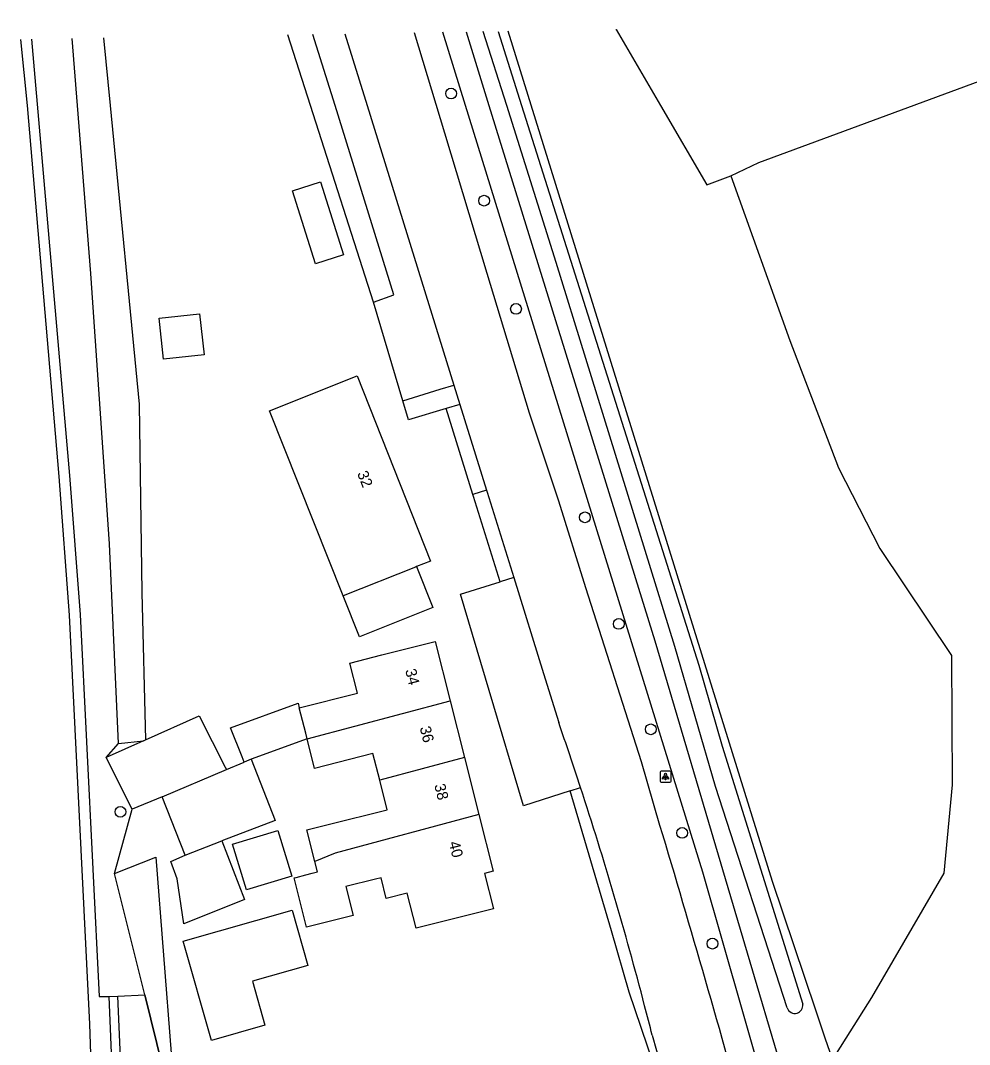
# Model space of a CAD drawing. Extents: x 162515 to 163909, y 388494 to 389773.
# Drawn here: x 162585.3 to 162671.5, y 389664.8 to 389757.7 of the extents above; entities that cross this region are included whole.
import ezdxf

# ---------------------------------------------------------------- set-up
doc = ezdxf.new("R2010")
doc.units = 0
for name, color, linetype in [('IMGEO_Boom', 7, 'Continuous'), ('IMGEO_Fietspad_gesloten', 7, 'Continuous'), ('IMGEO_Grasland_agrarisch', 7, 'Continuous'), ('IMGEO_Grasland_overig', 7, 'Continuous'), ('IMGEO_Groenvoorziening', 7, 'Continuous'), ('IMGEO_Haag', 7, 'Continuous'), ('IMGEO_Hek', 7, 'Continuous'), ('IMGEO_Lichtpunt', 7, 'Continuous'), ('IMGEO_Pand', 7, 'Continuous'), ('IMGEO_Pand_nummerreeks', 7, 'Continuous'), ('IMGEO_Rijbaan_lokaal_gesloten', 7, 'Continuous'), ('IMGEO_Rijbaan_lokaal_halfverhard', 7, 'Continuous'), ('IMGEO_Rijbaan_lokaal_open', 7, 'Continuous'), ('IMGEO_Rijbaan_regionaal_gesloten', 7, 'Continuous'), ('IMGEO_Voetpad_halfverhard', 7, 'Continuous'), ('IMGEO_Waterloop', 7, 'Continuous')]:
    doc.layers.add(name, color=color, linetype=linetype)

msp = doc.modelspace()

# ---------------------------------------------------------------- linework, layer by layer
at = {"layer": 'IMGEO_Boom'}
for centre in [(162624.392, 389751.1), (162627.393, 389741.373), (162630.292, 389731.545), (162636.548, 389712.625), (162639.625, 389702.949), (162642.53, 389693.381), (162594.354, 389685.892), (162645.384, 389683.977), (162648.134, 389673.926)]:
    msp.add_circle(centre, 0.489, dxfattribs=at)
at = {"layer": 'IMGEO_Fietspad_gesloten'}
for points in [[(162657.306, 389644.486), (162657.276, 389644.598), (162654.694, 389654.432), (162647.267, 389680.414), (162625.711, 389750), (162623.648, 389756.662)], [(162625.756, 389756.697), (162627.834, 389750), (162642.905, 389701.409), (162656.158, 389656.625)]]:
    msp.add_lwpolyline(points, dxfattribs=at)
at = {"layer": 'IMGEO_Grasland_agrarisch'}
for points in [[(162649.788, 389743.642), (162652.361, 389744.846), (162687.277, 389757.733)], [(162649.788, 389743.642), (162655.173, 389728.688), (162659.589, 389717.108), (162663.344, 389709.783), (162669.846, 389700.093), (162669.917, 389688.356), (162669.136, 389680.314), (162662.579, 389669.049), (162659.003, 389663.387)]]:
    msp.add_lwpolyline(points, dxfattribs=at)
at = {"layer": 'IMGEO_Grasland_overig'}
for points in [[(162593.826, 389680.304), (162597.563, 389681.786), (162598.974, 389663.973), (162599.575, 389661.2), (162600.194, 389654.868)], [(162596.561, 389669.268), (162593.826, 389680.304)], [(162596.561, 389669.268), (162599.268, 389658.347), (162600.194, 389654.868)]]:
    msp.add_lwpolyline(points, dxfattribs=at)
at = {"layer": 'IMGEO_Groenvoorziening'}
for points in [[(162659.003, 389663.387), (162658.792, 389664.143), (162658.415, 389665.263), (162657.534, 389667.881), (162653.602, 389679.561), (162629.565, 389756.763)], [(162639.372, 389756.927), (162639.379, 389756.914), (162643.424, 389750), (162647.635, 389742.802), (162649.788, 389743.642)], [(162586.279, 389756.033), (162589.745, 389716.421), (162590.687, 389703.802), (162592.43, 389669.135), (162593.333, 389669.135)], [(162620.012, 389723.199), (162617.339, 389732.159)], [(162626.377, 389714.707), (162623.952, 389722.498)], [(162593.056, 389690.825), (162594.171, 389692.08)], [(162593.826, 389680.304), (162595.429, 389686.12)], [(162594.132, 389669.168), (162596.561, 389669.268)]]:
    msp.add_lwpolyline(points, dxfattribs=at)
at = {"layer": 'IMGEO_Haag'}
for points in [[(162593.333, 389669.135), (162594.132, 389669.168)], [(162595.134, 389637.214), (162594.772, 389645.635), (162593.95, 389654.473), (162593.333, 389669.135)], [(162595.932, 389637.293), (162595.57, 389645.689), (162594.748, 389654.527), (162594.132, 389669.168)]]:
    msp.add_lwpolyline(points, dxfattribs=at)
at = {"layer": 'IMGEO_Hek'}
for points in [[(162593.826, 389680.304), (162597.563, 389681.786)], [(162596.561, 389669.268), (162593.826, 389680.304)], [(162600.194, 389654.868), (162599.268, 389658.347), (162596.561, 389669.268)]]:
    msp.add_lwpolyline(points, dxfattribs=at)
at = {"layer": 'IMGEO_Lichtpunt'}
for p, q in [((162643.373, 389689.494), (162643.373, 389688.687)), ((162643.373, 389689.494), (162643.373, 389688.687)), ((162644.275, 389689.589), (162643.467, 389689.589)), ((162644.275, 389689.589), (162643.467, 389689.589)), ((162644.369, 389688.687), (162644.369, 389689.494)), ((162644.369, 389688.687), (162644.369, 389689.494)), ((162643.467, 389688.593), (162644.275, 389688.593)), ((162643.467, 389688.593), (162644.275, 389688.593))]:
    msp.add_line(p, q, dxfattribs=at)
for points in [[(162643.747, 389689.158), (162643.786, 389689.13), (162643.598, 389688.868), (162643.56, 389688.895), (162643.747, 389689.158)], [(162643.849, 389689.11), (162643.896, 389689.11), (162643.896, 389688.788), (162643.849, 389688.788), (162643.849, 389689.11)], [(162643.959, 389689.13), (162643.997, 389689.157), (162644.184, 389688.895), (162644.145, 389688.867), (162643.959, 389689.13)]]:
    msp.add_lwpolyline(points, dxfattribs=at)
msp.add_circle((162643.872, 389689.292), 0.0994, dxfattribs=at)
for centre, start, end in [((162643.467, 389689.494), 90, 180), ((162643.467, 389689.494), 90, 180), ((162644.275, 389689.494), 0, 90), ((162644.275, 389689.494), 0, 90), ((162643.467, 389688.687), 180, 270), ((162643.467, 389688.687), 180, 270), ((162644.275, 389688.687), 270, 0), ((162644.275, 389688.687), 270, 360)]:
    msp.add_arc(centre, 0.0946, start, end, dxfattribs=at)
at = {"layer": 'IMGEO_Pand'}
for points in [[(162609.981, 389742.277), (162612.545, 389743.081), (162614.626, 389736.448), (162612.061, 389735.643), (162609.981, 389742.277)], [(162598.275, 389726.987), (162597.869, 389730.701), (162601.554, 389731.103), (162601.959, 389727.389), (162598.275, 389726.987)], [(162614.591, 389705.496), (162607.907, 389722.307), (162615.852, 389725.465), (162622.536, 389708.654), (162621.265, 389708.149)], [(162621.265, 389708.149), (162621.152, 389708.104), (162614.591, 389705.496)], [(162621.265, 389708.149), (162622.743, 389704.431), (162616.069, 389701.778), (162614.591, 389705.496)], [(162610.605, 389695.335), (162615.887, 389696.671), (162615.181, 389699.399), (162618.089, 389700.135), (162622.936, 389701.361), (162624.3, 389695.971)], [(162611.317, 389692.522), (162624.3, 389695.971)], [(162624.3, 389695.971), (162625.603, 389690.821)], [(162605.601, 389690.405), (162605.508, 389690.639), (162605.409, 389690.888), (162604.368, 389693.513), (162610.501, 389695.746), (162610.605, 389695.335)], [(162611.317, 389692.522), (162611.188, 389693.03), (162610.605, 389695.335)], [(162596.643, 389692.431), (162601.515, 389694.611), (162603.867, 389689.948), (162603.981, 389689.723)], [(162596.457, 389692.347), (162593.056, 389690.825)], [(162596.457, 389692.347), (162596.643, 389692.431)], [(162611.317, 389692.522), (162606.219, 389690.666)], [(162617.91, 389688.761), (162617.299, 389691.177), (162611.997, 389689.835), (162611.317, 389692.522)], [(162595.429, 389686.12), (162593.056, 389690.825)], [(162606.219, 389690.666), (162608.426, 389685.101), (162603.581, 389683.243)], [(162603.981, 389689.723), (162605.601, 389690.405)], [(162606.219, 389690.666), (162605.601, 389690.405)], [(162625.603, 389690.821), (162617.91, 389688.761)], [(162625.603, 389690.821), (162626.911, 389685.654)], [(162598.138, 389687.261), (162603.981, 389689.723)], [(162612.029, 389681.374), (162611.304, 389684.242), (162613.217, 389684.726), (162618.587, 389686.084), (162617.91, 389688.761)], [(162598.138, 389687.261), (162595.429, 389686.12)], [(162600.239, 389681.962), (162598.138, 389687.261)], [(162626.911, 389685.654), (162628.217, 389680.492), (162627.441, 389680.296), (162628.251, 389677.097), (162621.222, 389675.319), (162620.413, 389678.518), (162618.51, 389678.037), (162618.038, 389679.908), (162617.516, 389679.776), (162614.83, 389679.097), (162615.49, 389676.489), (162611.263, 389675.42), (162610.133, 389679.889), (162610.332, 389679.939), (162611.202, 389680.161), (162611.785, 389680.309), (162612.267, 389680.432), (162612.029, 389681.374)], [(162626.911, 389685.654), (162613.873, 389682.136), (162612.029, 389681.374)], [(162609.932, 389680.059), (162605.823, 389678.797), (162604.551, 389682.941), (162608.66, 389684.203), (162609.932, 389680.059)], [(162603.581, 389683.243), (162605.613, 389677.944), (162600.102, 389675.712), (162599.507, 389679.81), (162598.929, 389681.368), (162600.239, 389681.962)], [(162600.239, 389681.962), (162603.581, 389683.243)], [(162609.959, 389676.965), (162611.384, 389671.941), (162606.351, 389670.514), (162607.487, 389666.51), (162602.619, 389665.13), (162600.059, 389674.158), (162609.959, 389676.965)]]:
    msp.add_lwpolyline(points, dxfattribs=at)
at = {"layer": 'IMGEO_Rijbaan_lokaal_gesloten'}
for points in [[(162614.746, 389756.512), (162616.763, 389750), (162624.646, 389724.639)], [(162643.356, 389684.664), (162641.701, 389690.442), (162636.629, 389706.24), (162634.181, 389714.087), (162631.516, 389722.082), (162627.663, 389734.752), (162623.811, 389747.513), (162621.069, 389756.619)], [(162624.646, 389724.639), (162625.196, 389722.87)], [(162625.196, 389722.87), (162627.614, 389715.092)], [(162627.614, 389715.092), (162627.673, 389714.901), (162630.082, 389707.151)], [(162630.082, 389707.151), (162632.791, 389698.435), (162634.173, 389693.988)], [(162642.662, 389665.619), (162643.825, 389661.448)]]:
    msp.add_lwpolyline(points, dxfattribs=at)
for centre, radius, start, end in [((162310.638, 389581.786), 342.438, 18.08773, 19.12653), ((162307.447, 389580.769), 345.788, 14.66153, 18.08373), ((161544.624, 389352.917), 1147.723, 15.337949, 16.800985), ((162297.232, 389578.23), 356.312, 14.19723, 14.64087)]:
    msp.add_arc(centre, radius, start, end, dxfattribs=at)
at = {"layer": 'IMGEO_Rijbaan_lokaal_halfverhard'}
msp.add_lwpolyline([(162642.776, 389663.003), (162640.565, 389669.518), (162638.969, 389675.09), (162635.223, 389687.803)], dxfattribs=at)
at = {"layer": 'IMGEO_Rijbaan_lokaal_open'}
for points in [[(162627.614, 389715.092), (162626.377, 389714.707)], [(162628.847, 389706.767), (162626.436, 389714.516), (162626.377, 389714.707)], [(162630.082, 389707.151), (162628.847, 389706.767)], [(162635.223, 389687.803), (162630.982, 389686.434), (162627.859, 389696.902), (162625.249, 389705.649), (162628.847, 389706.767)], [(162635.223, 389687.803), (162636.154, 389688.104)]]:
    msp.add_lwpolyline(points, dxfattribs=at)
at = {"layer": 'IMGEO_Rijbaan_regionaal_gesloten'}
msp.add_lwpolyline([(162585.277, 389756.016), (162585.894, 389750), (162588.748, 389716.34), (162589.689, 389703.74), (162591.556, 389666.599), (162592.218, 389646.716), (162592.389, 389636.944)], dxfattribs=at)
at = {"layer": 'IMGEO_Voetpad_halfverhard'}
for points in [[(162620.012, 389723.199), (162623.405, 389724.253), (162624.646, 389724.639)], [(162623.952, 389722.498), (162620.528, 389721.472), (162620.012, 389723.199)], [(162625.196, 389722.87), (162623.952, 389722.498)]]:
    msp.add_lwpolyline(points, dxfattribs=at)
at = {"layer": 'IMGEO_Waterloop'}
for points in [[(162617.339, 389732.159), (162611.612, 389750), (162609.55, 389756.425)], [(162617.339, 389732.159), (162619.198, 389732.84), (162613.856, 389750), (162611.844, 389756.463)], [(162654.908, 389668.091), (162648.424, 389688.196), (162644.71, 389700.887), (162633.95, 389735.77), (162629.441, 389750), (162627.311, 389756.724)], [(162628.661, 389756.746), (162630.798, 389750), (162646.883, 389699.203), (162649.01, 389691.856), (162656.336, 389668.425)], [(162594.171, 389692.08), (162593.36, 389710.21), (162591.667, 389734.757), (162590.465, 389750), (162589.984, 389756.095)], [(162592.82, 389756.143), (162593.42, 389750), (162596.065, 389722.909), (162596.294, 389705.791), (162596.643, 389692.431)], [(162594.171, 389692.08), (162596.457, 389692.347)]]:
    msp.add_lwpolyline(points, dxfattribs=at)
for centre, radius, start, end in [((162655.643, 389668.371), 0.786, 200.89435, 282.58714), ((162655.556, 389668.344), 0.784, 289.18667, 5.91611)]:
    msp.add_arc(centre, radius, start, end, dxfattribs=at)

# ---------------------------------------------------------------- texts
at = {"layer": 'IMGEO_Pand_nummerreeks'}
for s, rotation, p in [('32', 291.68051, (162615.84, 389716.619)), ('34', 284.20341, (162620.214, 389698.748)), ('36', 284.20086, (162621.534, 389693.532)), ('38', 284.20086, (162622.855, 389688.311)), ('40', 284.20341, (162624.175, 389683.093))]:
    msp.add_text(s, height=1, rotation=rotation, dxfattribs=at).set_placement(p)

doc.saveas('drawing.dxf')
